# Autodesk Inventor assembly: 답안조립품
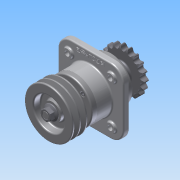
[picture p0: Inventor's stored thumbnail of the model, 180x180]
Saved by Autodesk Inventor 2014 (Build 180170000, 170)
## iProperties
Created: 2015-09
Part Number: 답안조립품
Document SubType Name: Assembly
Designer: study
Author: study
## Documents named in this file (12)
- C:\Users\study\Desktop\450909V1020\답안조립품.iam
- C:\Users\study\Desktop\450909V1020\1-본체.ipt
- C:\Users\study\Desktop\450909V1020\6-베어링 6206.ipt
- C:\Users\study\Desktop\450909V1020\2-커버.ipt
- C:\Users\study\Desktop\450909V1020\8-오일실 30x42.ipt
- C:\Users\study\Desktop\450909V1020\3-축.ipt
- C:\Users\study\Desktop\450909V1020\7-부시.ipt
- C:\Users\study\Desktop\450909V1020\10-M6.ipt
- C:\Users\study\Desktop\450909V1020\11-키 6x6.ipt
- C:\Users\study\Desktop\450909V1020\4-V벨트풀리.ipt
- C:\Users\study\Desktop\450909V1020\9-M16-너트.ipt
- C:\Users\study\Desktop\450909V1020\5-체인 스프로킷.ipt
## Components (23 placed, 11 different names)
1. 1-본체:1
2. 6-베어링 6206:1
3. 6-베어링 6206:2
4. 2-커버:1
5. 2-커버:2
6. 8-8-오일실 30x42:1
7. 8-8-오일실 30x42:2
8. 3-축:1 — 각도:1, 각도:2
9. 7-부시:1
10. 11-키 6x6:1 — 각도:1, 각도:3
11. 11-키 6x6:2 — 각도:2, 각도:4
12. 4-V벨트풀리:1 — 각도:3
13. 9-M16 너트:1
14. 5-체인 스프로킷:1 — 각도:4
15. 9-M16 너트:2
16. 10-M6:1
17. 10-M6:2
18. 10-M6:3
19. 10-M6:4
20. 10-M6:5
21. 10-M6:6
22. 10-M6:7
23. 10-M6:8
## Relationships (4: Angle 4)
- 각도:1 [Angle]: 3-축:1 ↔ 11-키 6x6:1
- 각도:2 [Angle]: 3-축:1 ↔ 11-키 6x6:2
- 각도:3 [Angle]: 11-키 6x6:1 ↔ 4-V벨트풀리:1
- 각도:4 [Angle]: 11-키 6x6:2 ↔ 5-체인 스프로킷:1
